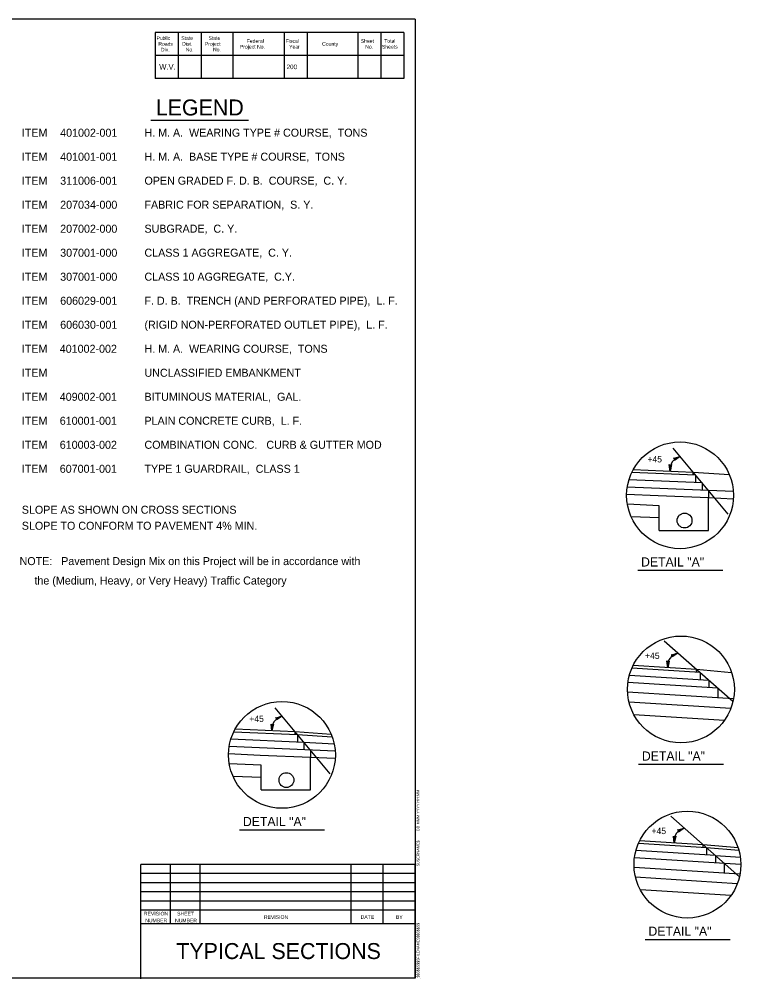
# Model space of a CAD drawing. Extents: x -592 to 1199, y -590 to 416.
# Drawn here: x 83.4 to 241.2, y -588.7 to -378.9 of the extents above; entities that cross this region are included whole.
import ezdxf

# ---------------------------------------------------------------- set-up
doc = ezdxf.new("R2010")
doc.units = 0
doc.layers.add('1', color=7, linetype='Continuous')
doc.layers.add('Des_ Drain_ Ftrs', color=7, linetype='Continuous')

msp = doc.modelspace()

# ---------------------------------------------------------------- linework, layer by layer
at = {"layer": '1'}
for p, q in [((170.03, -378.86), (-149.97, -378.86)), ((170.03, -378.86), (170.03, -588.62)), ((170.03, -378.86), (170.03, -378.86)), ((113.19, -381.74), (113.19, -391.8)), ((167.53, -381.74), (113.19, -381.74)), ((118.22, -381.74), (118.22, -391.8)), ((123.25, -381.74), (123.25, -391.8)), ((130.14, -381.74), (130.14, -391.8)), ((141.36, -381.74), (141.36, -391.8)), ((146.4, -381.74), (146.4, -391.8)), ((157.47, -381.74), (157.47, -391.8)), ((162.5, -381.74), (162.5, -391.8)), ((167.53, -381.74), (167.53, -391.8)), ((167.53, -386.78), (113.19, -386.78)), ((167.53, -391.8), (113.19, -391.8)), ((112.23, -400.94), (133.6, -400.94)), ((238.47, -487.15), (226.45, -472.68)), ((231.34, -478.6), (217.4, -477.99)), ((230.85, -477.98), (217.7, -477.41)), ((230.85, -478.58), (230.85, -477.98)), ((238.74, -478.55), (230.85, -477.98)), ((232.76, -480.28), (216.78, -479.58)), ((231.34, -478.6), (231.34, -480.23)), ((232.75, -480.28), (232.75, -481.89)), ((239.59, -482.2), (216.41, -481.19)), ((234.16, -481.96), (234.16, -483.58)), ((223.19, -483.1), (216.27, -482.8)), ((234.16, -483.58), (223.19, -483.1)), ((234.16, -490.66), (234.16, -483.58)), ((239.59, -483.82), (234.16, -483.58)), ((223.38, -485.27), (216.44, -484.96)), ((223.38, -490.66), (223.38, -485.27)), ((223.38, -485.27), (223.38, -485.27)), ((223.38, -487.96), (217.26, -487.69)), ((223.38, -490.66), (234.16, -490.66)), ((218.68, -499.38), (237.27, -499.38)), ((239.51, -528.1), (224.49, -514.88)), ((231.57, -521.13), (217.68, -520.25)), ((234.25, -523.48), (216.87, -522.39)), ((232.31, -521.76), (217.41, -520.83)), ((231.57, -521.72), (231.57, -521.12)), ((239.23, -521.8), (231.57, -521.12)), ((232.31, -521.76), (232.31, -523.36)), ((236.2, -525.2), (216.56, -523.96)), ((234.25, -523.48), (234.25, -525.07)), ((239.63, -527.51), (216.48, -526.06)), ((236.2, -525.2), (236.2, -527.3)), ((239.04, -529.62), (216.79, -528.22)), ((151.41, -543.92), (139.39, -529.46)), ((237.64, -532.23), (217.86, -530.99)), ((144.29, -535.38), (130.34, -534.77)), ((143.79, -534.76), (130.64, -534.18)), ((151.69, -535.32), (143.79, -534.76)), ((143.79, -535.36), (143.79, -534.76)), ((145.7, -537.06), (129.72, -536.36)), ((144.29, -535.38), (144.29, -537.01)), ((151.9, -535.88), (144.29, -535.38)), ((145.69, -537.06), (145.69, -538.66)), ((152.33, -537.42), (145.69, -537.06)), ((152.54, -538.97), (129.36, -537.96)), ((147.1, -538.74), (147.1, -540.35)), ((136.13, -539.87), (129.22, -539.57)), ((147.1, -540.35), (136.13, -539.87)), ((147.1, -547.43), (147.1, -540.35)), ((152.54, -540.59), (147.1, -540.35)), ((136.32, -542.04), (129.38, -541.74)), ((136.32, -547.43), (136.32, -542.04)), ((136.32, -542.04), (136.32, -542.04)), ((218.87, -541.83), (237.46, -541.83)), ((136.32, -544.74), (130.2, -544.47)), ((136.32, -547.43), (147.1, -547.43)), ((240.93, -566.43), (225.91, -553.21)), ((131.62, -556.15), (150.21, -556.15)), ((233.73, -560.09), (218.83, -559.15)), ((232.99, -559.45), (219.1, -558.58)), ((232.99, -560.04), (232.99, -559.44)), ((240.65, -560.13), (232.99, -559.44)), ((233.73, -560.09), (233.73, -561.68)), ((240.82, -560.68), (233.73, -560.09)), ((241.23, -563.75), (217.98, -562.28)), ((235.67, -561.8), (218.29, -560.71)), ((235.67, -561.8), (235.67, -563.4)), ((241.13, -562.22), (235.7, -561.83)), ((110.03, -588.74), (110.03, -563.75)), ((170.03, -563.75), (110.03, -563.75)), ((116.53, -576.74), (116.53, -563.75)), ((123.04, -576.74), (123.04, -563.75)), ((156.03, -576.74), (156.03, -563.75)), ((163.03, -576.74), (163.03, -563.75)), ((170.03, -588.62), (170.03, -563.75)), ((241.05, -565.84), (217.9, -564.38)), ((237.62, -563.52), (237.62, -565.62)), ((170.03, -565.75), (110.03, -565.75)), ((240.46, -567.94), (218.21, -566.54)), ((170.03, -567.74), (110.03, -567.74)), ((170.03, -569.75), (110.03, -569.75)), ((239.06, -570.56), (219.28, -569.31)), ((170.03, -571.74), (110.03, -571.74)), ((170.03, -573.74), (110.03, -573.74)), ((170.03, -576.74), (110.03, -576.74)), ((220.29, -580.15), (238.88, -580.15)), ((170.03, -588.62), (-149.97, -588.62)), ((170.03, -588.62), (170.03, -588.62)), ((171.13, -588.75), (171.13, -588.75)), ((171.13, -588.75), (171.13, -588.75))]:
    msp.add_line(p, q, dxfattribs=at)
for centre, radius in [((227.95, -483), 11.68), ((228.93, -488.51), 1.62), ((228.14, -525.45), 11.68), ((140.89, -539.77), 11.68), ((141.87, -545.29), 1.62), ((229.56, -563.77), 11.68)]:
    msp.add_circle(centre, radius, dxfattribs=at)
for centre in [(228.61, -477.33), (228.09, -520.3), (141.56, -534.11), (229.51, -558.62)]:
    msp.add_arc(centre, 2.88, 102.7123, 188.5092, dxfattribs=at)
at = {"layer": 'Des_ Drain_ Ftrs'}
for points in [[(225.76, -477.76), (225.6, -476.26), (225.83, -476.57), (226.09, -476.29)], [(227.98, -474.52), (226.72, -475.36), (226.89, -475.01), (226.52, -474.91)], [(227.45, -517.49), (226.2, -518.33), (226.37, -517.98), (225.99, -517.88)], [(225.24, -520.73), (225.07, -519.23), (225.31, -519.54), (225.57, -519.26)], [(138.71, -534.53), (138.54, -533.03), (138.77, -533.34), (139.04, -533.06)], [(140.92, -531.3), (139.67, -532.14), (139.84, -531.79), (139.46, -531.69)], [(228.87, -555.81), (227.62, -556.66), (227.79, -556.31), (227.41, -556.2)], [(226.66, -559.05), (226.49, -557.55), (226.72, -557.86), (226.99, -557.58)]]:
    msp.add_lwpolyline(points, close=True, dxfattribs=at)

# ---------------------------------------------------------------- texts
at = {"layer": '1'}
for s, height, p in [('Public', 0.8, (113.46, -383.4)), ('Roads', 0.8, (113.86, -384.66)), ('State', 0.8, (118.88, -383.4)), ('Dist.', 0.8, (119.07, -384.66)), ('Project', 0.8, (124.05, -384.66)), ('State', 0.8, (124.84, -383.4)), ('Federal', 0.8, (133.2, -384.03)), ('Fiscal', 0.8, (141.73, -384.03)), ('County', 0.8, (149.68, -384.66)), ('Sheet', 0.8, (158.13, -384.03)), ('Total', 0.8, (163.26, -384.03)), ('Div.', 0.8, (114.43, -385.92)), ('No.', 0.8, (119.86, -385.92)), ('No.', 0.8, (125.82, -385.92)), ('Project No.', 0.8, (131.7, -385.29)), ('Year', 0.8, (142.47, -385.29)), ('No.', 0.8, (159.11, -385.29)), ('Sheets', 0.8, (162.77, -385.29)), ('W.V.', 1.2, (114.06, -389.89)), ('200 ', 1, (141.9, -389.79)), ('LEGEND', 3.5, (113.3, -399.92)), ('ITEM', 1.75, (84.01, -404.57)), ('401002-001', 1.75, (92.4, -404.57)), ('H. M. A.  WEARING TYPE # COURSE,  TONS         ', 1.75, (110.83, -404.56)), ('ITEM', 1.75, (84.01, -409.82)), ('401001-001', 1.75, (92.4, -409.82)), ('H. M. A.  BASE TYPE # COURSE,  TONS               ', 1.75, (110.83, -409.81)), ('ITEM', 1.75, (84.01, -415.07)), ('311006-001', 1.75, (92.4, -415.07)), ('OPEN GRADED F. D. B.  COURSE,  C. Y.         ', 1.75, (110.83, -415.06)), ('ITEM', 1.75, (84.01, -420.32)), ('207034-000', 1.75, (92.4, -420.32)), ('FABRIC FOR SEPARATION,  S. Y.             ', 1.75, (110.83, -420.31)), ('ITEM', 1.75, (84.01, -425.57)), ('207002-000', 1.75, (92.4, -425.57)), ('SUBGRADE,  C. Y.                         ', 1.75, (110.83, -425.56)), ('ITEM', 1.75, (84.01, -430.82)), ('307001-000', 1.75, (92.4, -430.82)), ('CLASS 1 AGGREGATE,  C. Y.               ', 1.75, (110.83, -430.81)), ('ITEM', 1.75, (84.01, -436.07)), ('307001-000', 1.75, (92.4, -436.07)), ('CLASS 10 AGGREGATE,  C.Y.                 ', 1.75, (110.83, -436.06)), ('ITEM', 1.75, (84.01, -441.32)), ('606029-001', 1.75, (92.4, -441.32)), ('F. D. B.  TRENCH (AND PERFORATED PIPE),  L. F.', 1.75, (110.83, -441.31)), ('ITEM', 1.75, (84.01, -446.57)), ('606030-001', 1.75, (92.4, -446.57)), ('(RIGID NON-PERFORATED OUTLET PIPE),  L. F.  ', 1.75, (110.83, -446.56)), ('ITEM', 1.75, (84.01, -451.82)), ('401002-002', 1.75, (92.31, -451.82)), ('H. M. A.  WEARING COURSE,  TONS    ', 1.75, (110.83, -451.82)), ('ITEM', 1.75, (84.01, -457.07)), ('UNCLASSIFIED EMBANKMENT              ', 1.75, (110.83, -457.07)), ('ITEM', 1.75, (84.01, -462.32)), ('409002-001', 1.75, (92.31, -462.32)), ('BITUMINOUS MATERIAL,  GAL.           ', 1.75, (110.83, -462.32)), ('ITEM', 1.75, (84.01, -467.57)), ('610001-001', 1.75, (92.31, -467.57)), ('PLAIN CONCRETE CURB,  L. F.          ', 1.75, (110.83, -467.57)), ('ITEM', 1.75, (84.01, -472.82)), ('610003-002', 1.75, (92.31, -472.82)), ('COMBINATION CONC.   CURB & GUTTER MOD', 1.75, (110.83, -472.82)), ('ITEM', 1.75, (84.01, -478.07)), ('607001-001', 1.75, (92.31, -478.07)), ('TYPE 1 GUARDRAIL,  CLASS 1           ', 1.75, (110.83, -478.07)), ('+45', 1.4, (220.82, -475.81)), ('SLOPE AS SHOWN ON CROSS SECTIONS', 1.75, (84.01, -487.03)), ('SLOPE TO CONFORM TO PAVEMENT 4% MIN.', 1.75, (84.01, -490.53)), ('NOTE:   Pavement Design Mix on this Project will be in accordance with', 1.75, (83.52, -498.26)), ('DETAIL "A"', 2, (219.42, -498.57)), ('     the (Medium, Heavy, or Very Heavy) Traffic Category', 1.75, (83.52, -502.51)), ('+45', 1.4, (220.3, -518.78)), ('+45', 1.4, (133.76, -532.58)), ('DETAIL "A"', 2, (219.61, -541.02)), ('DETAIL "A"', 2, (132.36, -555.35)), ('+45', 1.4, (221.71, -557.1)), ('REVISION', 0.8, (110.71, -574.89)), ('SHEET', 0.8, (117.97, -574.89)), ('REVISION', 0.8, (136.96, -575.64)), ('DATE', 0.8, (158.11, -575.64)), ('BY', 0.8, (165.83, -575.64)), ('NUMBER', 0.8, (111.01, -576.39)), ('NUMBER', 0.8, (117.52, -576.39)), ('DETAIL "A"', 2, (221.03, -579.34)), ('TYPICAL SECTIONS', 3.5, (117.79, -584.43))]:
    msp.add_text(s, height=height, dxfattribs=at).set_placement(p)
for s, p in [('DD-MMM-YYYY HH:MM', (170.95, -556.45)), ('$USERNAME$', (170.95, -564.1)), ('$$$$$$$$$FILENAME$$$$$$$$', (170.95, -588.49))]:
    msp.add_text(s, height=0.6, rotation=90, dxfattribs=at).set_placement(p)

doc.saveas('drawing.dxf')
